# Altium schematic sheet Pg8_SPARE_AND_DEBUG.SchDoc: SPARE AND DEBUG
size 431 x 279 mm; Date: Not shown in title block; ApprovedBy: Not shown in title block; CheckedBy: Not shown in title block; Author: Not shown in title block; CompanyName: Not shown in title block; Engineer: Not shown in title block; Organization: Not shown in title block; Address1: Not shown in title block; Address2: Not shown in title block; Address3: Not shown in title block; Address4: Not shown in title block; DocumentNumber: 8; Revision: Use project parameter SCH_Rev; SheetNumber: 8; SheetTotal: 9; PageSetup: Record=PageOptions|CenterHorizontal=True|CenterVertical=True|PrintScale=1.00|XCorrection=1.00|YCorrection=1.00|PrintKind=0|BorderSize=5000000|LeftOffset=0|BottomOffset=0|Orientation=2|PaperLength=1000|PaperWidth=1000|Scale=100|PaperSource=15|PrintQuality=600|MediaType=1|DitherType=10|PaperKind=Letter|PrintScaleMode=1
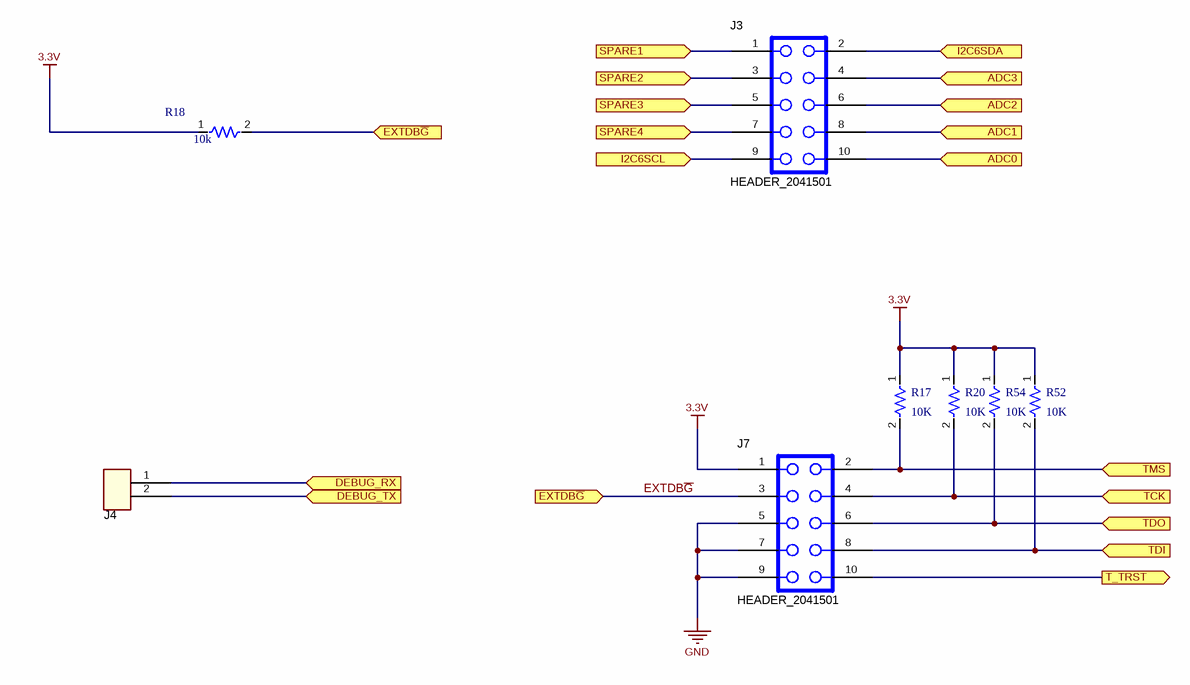
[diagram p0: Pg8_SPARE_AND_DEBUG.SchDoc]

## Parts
J3  HEADER_2041501  [HDR2X5 _2MM]
J4  CON-OSTVN02A150  [CN2_MTB_P100_PD80_D1.1_S5.54X6.5_STACK]  (value not drawn)
J7  HEADER_2041501  [HDR2X5 _2MM]
R17  value 10K  [0402]  (hidden comment: RESC0402)
R18  value 10k  [0402]  (hidden comment: RESC0402)
R20  value 10K  [0402]  (hidden comment: RESC0402)
R52  value 10K  [0402]  (hidden comment: RESC0402)
R54  value 10K  [0402]  (hidden comment: RESC0402)

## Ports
ADC0, ADC1, ADC2, ADC3, DEBUG_RX, DEBUG_TX, EXTDB~{G} (in), I2C6SCL, I2C6SDA, SPARE1, SPARE2, SPARE3, SPARE4, T_TRST, TCK, TDI, TDO, TMS

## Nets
3.3V: J7.1 R17.1 R18.1 R20.1 R52.1 R54.1
GND: J7.5 J7.7 J7.9
EXTDB~{G}: J7.3 R18.2 ; port EXTDB~{G}
ADC0: J3.10 ; port ADC0
ADC1: J3.8 ; port ADC1
ADC2: J3.6 ; port ADC2
ADC3: J3.4 ; port ADC3
DEBUG_RX: J4.1 ; port DEBUG_RX
DEBUG_TX: J4.2 ; port DEBUG_TX
I2C6SCL: J3.9 ; port I2C6SCL
I2C6SDA: J3.2 ; port I2C6SDA
SPARE1: J3.1 ; port SPARE1
SPARE2: J3.3 ; port SPARE2
SPARE3: J3.5 ; port SPARE3
SPARE4: J3.7 ; port SPARE4
T_TRST: J7.10 ; port T_TRST
TCK: J7.4 R20.2 ; port TCK
TDI: J7.8 R52.2 ; port TDI
TDO: J7.6 R54.2 ; port TDO
TMS: J7.2 R17.2 ; port TMS

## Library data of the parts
J3 J7 = HEADER_2041501: Header, 2X5 2mm spacing; PartNumber: M22-2020505; Manufacturer: Harwin Inc; Area: 55 mm
J4 = CON-OSTVN02A150: Terminal Block, 4x1, 2.54mm, TH; Manufacturer: On Shore Technology Inc; SymbolCreator: x0120606
R17 R18 R20 R52 R54 = RESC0402: Resistor, 10k ohm, 1/10W, 5%, 0402 Thick Film; Manufacturer #1: Generic; Part Number: RC0402FR-0710KL; Description: Resistor,Chip;1.00mm L X 0.5mm W X 0.35mm H; Geometry.Height: 0.35mm; PCBL.Component: CHP;RESC;1500;1700;150;400;700;950;600; PCBL.Process: F;N;50;50;200;100;200;250;350;-50;0; PCB DECAL: RESC0402N; GNUM: G11-R0402-1002-AAA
